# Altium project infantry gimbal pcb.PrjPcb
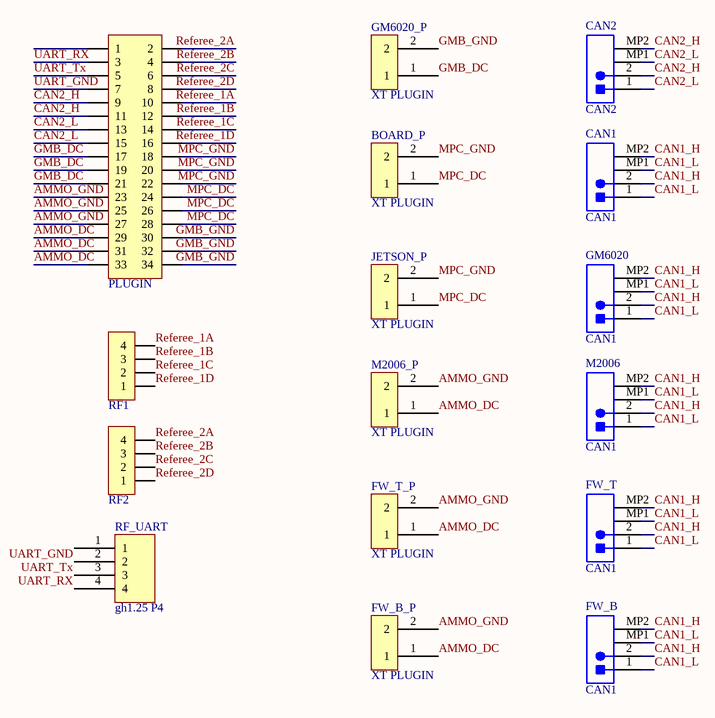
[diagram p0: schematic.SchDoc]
1 sheet, 16 parts. Net scope: global (net labels, ports and power ports of the same name join across sheets).
Board file: infantry gimbal pcb.PcbDoc

## Sheet schematic.SchDoc
size A4

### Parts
BOARD_P  XT PLUGIN  [XT30-M]
CAN1  CAN1  [JST-BM02B-GHS-TBT_V]
CAN2  CAN2  [JST-BM02B-GHS-TBT_V]
FW_B  CAN1  [JST-BM02B-GHS-TBT_V]
FW_B_P  XT PLUGIN  [XT30-M]
FW_T  CAN1  [JST-BM02B-GHS-TBT_V]
FW_T_P  XT PLUGIN  [XT30-M]
GM6020  CAN1  [JST-BM02B-GHS-TBT_V]
GM6020_P  XT PLUGIN  [XT30-M]
JETSON_P  XT PLUGIN  [XT30-M]
M2006  CAN1  [JST-BM02B-GHS-TBT_V]
M2006_P  XT PLUGIN  [XT30-M]
PLUGIN  Header 2X11  [IDC2.54-LI-2x17P]  (value not drawn)
RF1  HDR-1X4  [KF2510-LI-4P]  (value not drawn)
RF2  HDR-1X4  [KF2510-LI-4P]  (value not drawn)
RF_UART  gh1.25 P4  [GH1.25-4PIN]

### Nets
AMMO_DC: FW_B_P.1 FW_T_P.1 M2006_P.1 PLUGIN.29 PLUGIN.31 PLUGIN.33
AMMO_GND: FW_B_P.2 FW_T_P.2 M2006_P.2 PLUGIN.23 PLUGIN.25 PLUGIN.27
CAN1_H: CAN1.2 CAN1.MP2 FW_B.2 FW_B.MP2 FW_T.2 FW_T.MP2 GM6020.2 GM6020.MP2 M2006.2 M2006.MP2
CAN1_L: CAN1.1 CAN1.MP1 FW_B.1 FW_B.MP1 FW_T.1 FW_T.MP1 GM6020.1 GM6020.MP1 M2006.1 M2006.MP1
CAN2_H: CAN2.2 CAN2.MP2 PLUGIN.9 PLUGIN.11
CAN2_L: CAN2.1 CAN2.MP1 PLUGIN.13 PLUGIN.15
GMB_DC: GM6020_P.1 PLUGIN.17 PLUGIN.19 PLUGIN.21
GMB_GND: GM6020_P.2 PLUGIN.30 PLUGIN.32 PLUGIN.34
MPC_DC: BOARD_P.1 JETSON_P.1 PLUGIN.24 PLUGIN.26 PLUGIN.28
MPC_GND: BOARD_P.2 JETSON_P.2 PLUGIN.18 PLUGIN.20 PLUGIN.22
Referee_1A: PLUGIN.10 RF1.4
Referee_1B: PLUGIN.12 RF1.3
Referee_1C: PLUGIN.14 RF1.2
Referee_1D: PLUGIN.16 RF1.1
Referee_2A: PLUGIN.2 RF2.4
Referee_2B: PLUGIN.4 RF2.3
Referee_2C: PLUGIN.6 RF2.2
Referee_2D: PLUGIN.8 RF2.1
UART_GND: PLUGIN.7 RF_UART.2
UART_RX: PLUGIN.3 RF_UART.4
UART_Tx: PLUGIN.5 RF_UART.3

Not connected (* = marked no-connect by the designer): PLUGIN 1; RF_UART 1

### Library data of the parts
CAN1 CAN2 FW_B FW_T GM6020 M2006 = CMP-2000-05957-1: Disconnectable Crimp Style Connector, Pitch 1.25 mm, 1 x 2 Position, Height 4.05 mm, -25 to 85 degC, RoHS, Tape and Reel; Manufacturer: JST-Sales-America-Inc.; Connector Type: Header,Shrouded; Number of Positions Loaded: All; Pitch: 0.049"(1.25mm); Number of Positions: 2
PLUGIN = Header 17X2: 17*2P接插件; 版权归属: 封装库来自淘宝 ID：黄晶宝石
RF1 RF2 = Header 4: 4P接插件; 版权归属: 封装库来自淘宝 ID：黄晶宝石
